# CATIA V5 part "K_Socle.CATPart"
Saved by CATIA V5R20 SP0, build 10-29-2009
Part number: Socle
Property "Longueur tige": 2320 mm
Property "diamètre joint": 20 mm
Property "Ecart tige": 200 mm
Bounding box of the stored display mesh (mm): x -200 to 900, y -150 to 150, z -200 to 3300
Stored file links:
  C:\Users\thinkmotion1\Desktop\Khaled_IAO_Pack2\Problemes\IAO_2010_1405_jpalas\IAO_PALAS\Khaled_Palas\K_Socle.CATPart
  C:\Users\thinkmotion1\Desktop\Khaled_IAO_Pack2\Problemes\IAO_2010_1405_jpalas\IAO_PALAS\Khaled_Palas\K_Palas.CATProduct
  C:\Users\Jep\Desktop\ifma\semestre 3\projet IAO\Modelisation catia\Squelette de base.CATPart
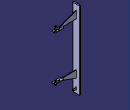
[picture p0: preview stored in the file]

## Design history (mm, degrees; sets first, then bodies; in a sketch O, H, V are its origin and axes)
Set1
  Point1: linked copy from another document
  Point2: linked copy from another document
Set2
  Plane1: type Offset, RefPlane face of Pad4, Offset 1000, reversed
Body1 (main body)
  Sketch1 on zx-plane, origin (0, 0, 0), H (0, 0, 1), V (1, 0, 0)
    arc A1 centre (0, 0) radius 20 from (19.5979, 3.9901) to (-19.644, 3.7569) ccw
    line L1 (-19.644, 3.7569) -> (-49.0497, -150)
    line L2 (-49.0497, -150) -> (50.9503, -150)
    line L3 (50.9503, -150) -> (19.5979, 3.9901)
    reference projected point E1 (0, 0) from Point1
    reference projected point E2 (0, 0) from Point2
    length L2 = 100
    radius A1 = 20
    distance E1 L2 = 150
    length L3 = 157.1494
    horizontal: L2 H
    tangency: L3 A1, L1 A1
    concentricity: E2 A1
  Pad1: profile Sketch1, direction (0, 1, 0), length 20
  Sketch2 on face of Pad1 from Sketch1.L2, origin (-150, 0, -49.0497), H (0, 0, 1), V (0, 1, 0)
    line L1 (-150.9503, 150) -> (3349.0497, 150)
    line L2 (3349.0497, 150) -> (3349.0497, -150)
    line L3 (3349.0497, -150) -> (-150.9503, -150)
    line L4 (-150.9503, -150) -> (-150.9503, 150)
    reference projected point E1 (49.0497, 0) from Point1
    reference projected point E2 (49.0497, 0) from Point1
    length L4 = 300
    distance E1 L4 = 200
    distance E2 L1 = 150
    length L3 = 3500
    horizontal: L1 H, L3 H
    vertical: L2 V, L4 V
  Pad2: profile Sketch2, direction (-1, 0, 0), length 50
  Sketch3 on end face of Pad1, origin (-22.4937, 20, 3.904), H (1, 0, 0), V (0, 0, -1)
    point P1 (22.4937, 3.904)
    reference projected point E1 (22.4937, 3.904) from Point1
    coincidence: P1 E1
  Hole1: placed by Sketch3, at (0, 20, 0) direction (0, -1, 0), diameter 20, through (limit type 3)
  Sketch4 on zx-plane, origin (0, 0, 0), H (0, 0, 1), V (1, 0, 0)
    point P1 (400, -150)
    line L1 (400, -150) -> (728.3882, -150)
    line L2 (728.3882, -150) -> (728.3882, 600)
    line L3 (728.3882, 600) -> (678.3882, 600)
    line L4 (678.3882, 600) -> (400, -150)
    point P5 (400, -150)
    reference projected line E1 (1800, -150) -> (-200, -150) from edge [start face of Pad2 | face of Pad2 from Sketch2.L1]
    reference projected line E2 (-200, -150) -> (-200, -200) from edge [face of Pad2 from Sketch2.L4 | face of Pad2 from Sketch2.L1]
    length L3 = 50
    length L2 = 750
    length L4 = 800
    distance P1 E2 = 600
    horizontal: L1 H, L3 H
    vertical: L2 V
    coincidence: P5 L1, L1 E1, P5 P1
  Pad3: profile Sketch4, direction (0, 1, 0), length 20
  Sketch5 on end face of Pad3, origin (0, 20, 0), H (0, 0, 1), V (1, 0, 0)
    line L1 (718.3882, 900) -> (728.3882, 900)
    line L2 (728.3882, 900) -> (728.3882, 500)
    line L3 (728.3882, 500) -> (718.3882, 500)
    line L4 (718.3882, 500) -> (718.3882, 900)
    reference projected line E1 (728.3882, 600) -> (678.3882, 600) from edge [face of Pad3 from Sketch4.L3 | end face of Pad3]
    reference projected line E2 (728.3882, -150) -> (728.3882, 600) from edge [face of Pad3 from Sketch4.L2 | end face of Pad3]
    length L1 = 10
    length L2 = 400
    distance E1 L1 = 300
    horizontal: L1 H, L3 H
    vertical: L2 V, L4 V
    coincidence: L2 E2
  Pad4: profile Sketch5, direction (0, 1, 0), length 80, opposite side length 70
  Sketch6 on end face of Pad3, origin (0, 20, 0), H (0, 0, 1), V (1, 0, 0)
    line L1 (718.3882, 800) -> (718.3882, 700)
    point P2 (718.3882, 700)
    line L2 (718.3882, 700) -> (564.5145, 730.3787)
    line L3 (718.3882, 800) -> (564.5145, 769.6213)
    arc A1 centre (568.3882, 750) radius 20 from (564.5145, 769.6213) to (564.5145, 730.3787) ccw
    point P5 (568.3882, 750)
    reference projected line E1 (718.3882, 800) -> (718.3882, 500) from edge [face of Pad4 from Sketch5.L4 | end face of Pad4]
    reference projected line E2 (728.3882, 600) -> (678.3882, 600) from edge [face of Pad3 from Sketch4.L3 | end face of Pad3]
    axis line L4 (568.3882, 750) -> (718.3882, 750)
    point P6 (718.3882, 750)
    radius A1 = 20
    distance P2 E2 = 100
    distance P5 L1 = 150
    length L1 = 100
    vertical: L1 V
    tangency: L3 A1, A1 L2
    coincidence: L1 E1
    midpoint: P6 L1
    perpendicularity: L4 L1
  Pad5: profile Sketch6, direction (0, -1, 0), length 45, opposite side length -25
  Sketch7 on start face of Pad5, origin (700.0822, -5, 573.7389), H (1, 0, 0), V (0, 0, -1)
    point P1 (49.9178, 5.3507)
    reference projected arc E1 centre (49.9178, 5.3507) radius 20 from (69.4568, 9.6203) to (30.3789, 9.6203) ccw from edge [face of Pad5 from Sketch6.A1 | start face of Pad5]
    concentricity: P1 E1
  Hole2: placed by Sketch7, at (750, -5, 568.3882) direction (0, -1, 0), diameter 20, through (limit type 3)
  Sketch8 on face of Pad4, origin (-150, 0, 728.3882), H (1, 0, 0), V (0, 1, 0)
    construction line L1 (855, 35) -> (795, 35)
    point P1 (855, 35)
    line L2 (855, 15) -> (795, 15)
    line L3 (795, 55) -> (855, 55)
    arc A1 centre (795, 35) radius 20 from (795, 15) to (795, 55) cw
    arc A2 centre (855, 35) radius 20 from (855, 55) to (855, 15) cw
    reference projected line E1 (850, -5) -> (950, -5) from edge [face of Pad4 from Sketch5.L4 | start face of Pad5]
    construction line L4 (945, 35) -> (1005, 35)
    line L5 (945, 55) -> (1005, 55)
    line L6 (1005, 15) -> (945, 15)
    arc A3 centre (1005, 35) radius 20 from (1005, 55) to (1005, 15) cw
    arc A4 centre (945, 35) radius 20 from (945, 15) to (945, 55) cw
    point P13 (825, 35)
    point P14 (850, 35)
    point P15 (825, 35)
    reference projected line E2 (850, -5) -> (850, -25) from edge [face of Pad5 from Sketch6.L2 | face of Pad4 from Sketch5.L4]
    point P16 (975, 35)
    reference projected line E3 (950, -5) -> (950, -25) from edge [face of Pad4 from Sketch5.L4 | face of Pad5 from Sketch6.L3]
    length L3 = 60
    distance P1 E1 = 40
    radius A2 = 20
    radius A4 = 20
    length L5 = 60
    distance P13 E2 = 25
    distance P16 E3 = 25
    radius A1 = 20
    radius A3 = 20
    horizontal: L1 H, L4 H
    tangency: A1 L2, A2 L2, A1 L3, A2 L3, A3 L5, A4 L5, A3 L6, A4 L6
    midpoint: P13 L1, P15 L1, P16 L4
    coincidence: P14 L1, P15 P13
  Pocket1: profile Sketch8, direction (0, 0, -1), length 10
  Mirror1: of Pad3, Sketch4, Pad4, Sketch5, Pad5, Sketch6, Hole2, Pocket1, Sketch8, about Plane1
